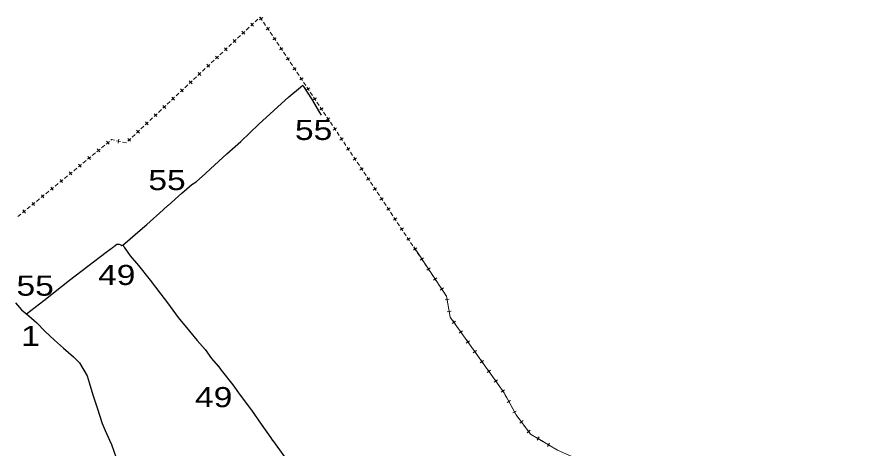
# Model space of a CAD drawing. Extents: x 476989 to 498418, y 4381813 to 4416555.
# Drawn here: x 485532 to 487660, y 4388253 to 4389328 of the extents above; entities that cross this region are included whole.
import ezdxf
from ezdxf.enums import TextEntityAlignment as Align

# ---------------------------------------------------------------- set-up
doc = ezdxf.new("R2010")
doc.units = 0
doc.header["$LTSCALE"] = 20
for name, color, linetype, lineweight in [('13', 7, 'Continuous', 13), ('34', 7, 'Continuous', 13), ('6', 7, 'Continuous', 25)]:
    doc.layers.add(name, color=color, linetype=linetype, lineweight=lineweight)

msp = doc.modelspace()

# ---------------------------------------------------------------- linework, layer by layer
at = {"layer": '34'}
for p, q in [((486136.45, 4389326.54), (486138, 4389328)), ((486144.93, 4389326.63), (486136.62, 4389321.07)), ((486138, 4389328), (486143.56, 4389319.7)), ((486114.56, 4389306.04), (486121.86, 4389312.87)), ((486114.79, 4389313.1), (486121.63, 4389305.81)), ((486125.51, 4389316.29), (486132.81, 4389323.13)), ((486146.34, 4389315.54), (486151.9, 4389307.23)), ((486092.68, 4389285.53), (486099.98, 4389292.37)), ((486092.91, 4389292.6), (486099.75, 4389285.3)), ((486103.63, 4389295.79), (486110.92, 4389302.62)), ((486161.61, 4389301.71), (486153.3, 4389296.15)), ((486154.67, 4389303.08), (486160.23, 4389294.77)), ((486163.01, 4389290.62), (486168.57, 4389282.3)), ((486070.8, 4389265.02), (486078.09, 4389271.86)), ((486071.03, 4389272.09), (486077.86, 4389264.79)), ((486081.74, 4389275.28), (486089.04, 4389282.12)), ((486178.28, 4389276.78), (486169.97, 4389271.22)), ((486171.35, 4389278.16), (486176.91, 4389269.85)), ((486179.69, 4389265.69), (486185.25, 4389257.38)), ((486048.91, 4389244.52), (486056.21, 4389251.35)), ((486049.14, 4389251.58), (486055.98, 4389244.29)), ((486059.86, 4389254.77), (486067.16, 4389261.61)), ((486194.96, 4389251.86), (486186.65, 4389246.3)), ((486188.02, 4389253.23), (486193.59, 4389244.92)), ((486016.09, 4389213.76), (486023.39, 4389220.6)), ((486027.03, 4389224.01), (486034.33, 4389230.85)), ((486027.26, 4389231.08), (486034.1, 4389223.78)), ((486037.98, 4389234.27), (486045.27, 4389241.1)), ((486196.37, 4389240.76), (486201.93, 4389232.45)), ((486211.64, 4389226.93), (486203.33, 4389221.37)), ((486204.7, 4389228.31), (486210.26, 4389219.99)), ((485994.21, 4389193.25), (486001.51, 4389200.09)), ((486005.15, 4389203.5), (486012.45, 4389210.34)), ((486005.38, 4389210.57), (486012.22, 4389203.27)), ((486213.04, 4389215.84), (486218.6, 4389207.53)), ((486228.31, 4389202.01), (486220, 4389196.44)), ((486221.38, 4389203.38), (486226.94, 4389195.07)), ((485972.33, 4389172.74), (485979.62, 4389179.58)), ((485983.27, 4389182.99), (485990.56, 4389189.83)), ((485983.5, 4389190.06), (485990.33, 4389182.77)), ((486229.72, 4389190.91), (486235.28, 4389182.6)), ((486238.06, 4389178.45), (486243.62, 4389170.14)), ((485950.45, 4389152.24), (485957.74, 4389159.08)), ((485961.38, 4389162.49), (485968.68, 4389169.33)), ((485961.61, 4389169.55), (485968.45, 4389162.26)), ((486244.99, 4389177.08), (486236.68, 4389171.52)), ((486246.4, 4389165.99), (486251.96, 4389157.68)), ((485928.56, 4389131.73), (485935.86, 4389138.57)), ((485939.5, 4389141.98), (485946.8, 4389148.82)), ((485939.73, 4389149.05), (485946.57, 4389141.75)), ((486261.67, 4389152.15), (486253.36, 4389146.59)), ((486254.73, 4389153.53), (486260.29, 4389145.22)), ((486263.07, 4389141.06), (486268.63, 4389132.75)), ((485906.68, 4389111.22), (485913.98, 4389118.06)), ((485917.62, 4389121.47), (485924.91, 4389128.31)), ((485917.85, 4389128.54), (485924.68, 4389121.24)), ((486278.35, 4389127.23), (486270.03, 4389121.67)), ((486271.41, 4389128.6), (486276.97, 4389120.29)), ((486279.75, 4389116.14), (486285.31, 4389107.83)), ((485884.8, 4389090.72), (485892.09, 4389097.55)), ((485895.73, 4389100.97), (485903.03, 4389107.8)), ((485895.96, 4389108.03), (485902.8, 4389100.74)), ((486295.02, 4389102.3), (486286.71, 4389096.74)), ((486288.09, 4389103.68), (486293.65, 4389095.37)), ((485862.91, 4389070.21), (485870.21, 4389077.05)), ((485873.85, 4389080.46), (485881.15, 4389087.3)), ((485874.08, 4389087.53), (485880.92, 4389080.23)), ((486296.43, 4389091.21), (486301.99, 4389082.9)), ((486311.7, 4389077.38), (486303.39, 4389071.82)), ((486304.76, 4389078.75), (486310.32, 4389070.44)), ((485841.03, 4389049.7), (485848.33, 4389056.54)), ((485851.97, 4389059.95), (485859.27, 4389066.79)), ((485852.2, 4389067.02), (485859.04, 4389059.72)), ((486313.1, 4389066.29), (486318.66, 4389057.97)), ((486328.38, 4389052.45), (486320.06, 4389046.89)), ((486321.44, 4389053.83), (486327, 4389045.52)), ((485819.15, 4389029.2), (485826.44, 4389036.03)), ((485830.09, 4389039.45), (485837.38, 4389046.28)), ((485830.31, 4389046.51), (485837.15, 4389039.22)), ((486329.78, 4389041.36), (486335.34, 4389033.05)), ((486338.12, 4389028.9), (486343.68, 4389020.59)), ((485743.01, 4389002.49), (485750.74, 4389008.83)), ((485754.59, 4389012), (485762.32, 4389018.34)), ((485755.29, 4389019.04), (485761.63, 4389011.31)), ((485780.35, 4389020.26), (485790.11, 4389018.09)), ((485786.31, 4389024.05), (485784.14, 4389014.29)), ((485808.2, 4389018.94), (485815.5, 4389025.78)), ((485808.43, 4389026.01), (485815.27, 4389018.71)), ((486345.05, 4389027.53), (486336.74, 4389021.97)), ((486346.46, 4389016.43), (486352.02, 4389008.12)), ((485719.82, 4388983.46), (485727.55, 4388989.81)), ((485731.41, 4388992.97), (485739.14, 4388999.32)), ((485732.1, 4389000.01), (485738.45, 4388992.28)), ((486361.73, 4389002.6), (486353.42, 4388997.04)), ((486354.79, 4389003.98), (486360.35, 4388995.66)), ((486363.13, 4388991.51), (486368.7, 4388983.2)), ((485696.64, 4388964.44), (485704.37, 4388970.78)), ((485708.23, 4388973.95), (485715.96, 4388980.29)), ((485708.92, 4388980.98), (485715.27, 4388973.25)), ((486378.41, 4388977.68), (486370.09, 4388972.11)), ((486371.47, 4388979.05), (486377.03, 4388970.74)), ((486379.81, 4388966.58), (486385.37, 4388958.27)), ((485673.46, 4388945.41), (485681.19, 4388951.76)), ((485685.05, 4388954.92), (485692.78, 4388961.27)), ((485685.74, 4388961.96), (485692.08, 4388954.23)), ((486395.08, 4388952.75), (486386.77, 4388947.19)), ((486388.15, 4388954.12), (486393.71, 4388945.81)), ((485638.68, 4388916.87), (485646.41, 4388923.22)), ((485639.37, 4388923.91), (485645.72, 4388916.18)), ((485650.28, 4388926.39), (485658.01, 4388932.73)), ((485661.86, 4388935.9), (485669.59, 4388942.24)), ((485662.56, 4388942.93), (485668.9, 4388935.2)), ((486396.49, 4388941.66), (486402.05, 4388933.35)), ((486411.76, 4388927.82), (486403.45, 4388922.26)), ((486404.82, 4388929.2), (486410.38, 4388920.89)), ((485615.5, 4388897.85), (485623.23, 4388904.19)), ((485616.19, 4388904.88), (485622.54, 4388897.15)), ((485627.09, 4388907.36), (485634.82, 4388913.71)), ((486413.16, 4388916.73), (486418.73, 4388908.42)), ((486428.44, 4388902.9), (486420.13, 4388897.34)), ((486421.5, 4388904.27), (486427.06, 4388895.96)), ((485592.32, 4388878.82), (485600.05, 4388885.16)), ((485593.01, 4388885.86), (485599.35, 4388878.13)), ((485603.91, 4388888.34), (485611.64, 4388894.68)), ((486429.84, 4388891.81), (486435.4, 4388883.5)), ((485569.13, 4388859.8), (485576.86, 4388866.14)), ((485569.83, 4388866.83), (485576.17, 4388859.1)), ((485580.73, 4388869.31), (485588.46, 4388875.66)), ((486445.11, 4388877.97), (486436.8, 4388872.41)), ((486438.18, 4388879.35), (486443.74, 4388871.04)), ((486446.52, 4388866.88), (486452.08, 4388858.57)), ((485534.36, 4388831.26), (485542.09, 4388837.6)), ((485545.95, 4388840.77), (485553.68, 4388847.11)), ((485546.64, 4388847.81), (485552.99, 4388840.08)), ((485557.55, 4388850.29), (485565.28, 4388856.63)), ((486461.79, 4388853.05), (486453.48, 4388847.49)), ((486454.85, 4388854.42), (486460.41, 4388846.11)), ((486463.2, 4388841.96), (486468.76, 4388833.64)), ((486478.47, 4388828.12), (486470.16, 4388822.56)), ((486471.53, 4388829.5), (486477.09, 4388821.19)), ((486479.87, 4388817.03), (486485.43, 4388808.72)), ((486495.14, 4388803.2), (486486.83, 4388797.64)), ((486488.21, 4388804.57), (486493.77, 4388796.26)), ((486496.55, 4388792.1), (486502.11, 4388783.79)), ((486511.82, 4388778.27), (486503.51, 4388772.71)), ((486504.88, 4388779.65), (486510.45, 4388771.33)), ((486513.23, 4388767.18), (486518.79, 4388758.87)), ((486528.5, 4388753.35), (486520.19, 4388747.78)), ((486521.56, 4388754.72), (486527.12, 4388746.41)), ((486529.9, 4388742.25), (486535.46, 4388733.94)), ((486545.17, 4388728.42), (486536.86, 4388722.86)), ((486538.24, 4388729.79), (486543.8, 4388721.48)), ((486546.58, 4388717.33), (486552.14, 4388709.02)), ((486561.85, 4388703.49), (486553.54, 4388697.93)), ((486554.91, 4388704.87), (486560.48, 4388696.56)), ((486563.26, 4388692.4), (486568.82, 4388684.09)), ((486578.53, 4388678.57), (486570.22, 4388673.01)), ((486571.59, 4388679.94), (486577.15, 4388671.63)), ((486579.93, 4388667.48), (486585.49, 4388659.17)), ((486595.2, 4388653.64), (486586.89, 4388648.08)), ((486588.27, 4388655.02), (486593.83, 4388646.71)), ((486596.61, 4388642.55), (486602.17, 4388634.24)), ((486609.38, 4388625.48), (486599.52, 4388623.77)), ((486603.6, 4388629.55), (486605.3, 4388619.7)), ((486606.15, 4388614.77), (486607.86, 4388604.92)), ((486614.49, 4388595.93), (486604.64, 4388594.22)), ((486608.71, 4388600), (486610.42, 4388590.15)), ((486625.19, 4388571.11), (486617.04, 4388565.31)), ((486618.21, 4388572.28), (486624.02, 4388564.14)), ((486626.92, 4388560.07), (486632.72, 4388551.92)), ((486642.59, 4388546.69), (486634.45, 4388540.89)), ((486635.62, 4388547.86), (486641.42, 4388539.72)), ((486644.33, 4388535.65), (486650.13, 4388527.5)), ((486660, 4388522.27), (486651.86, 4388516.47)), ((486653.03, 4388523.44), (486658.83, 4388515.3)), ((486661.73, 4388511.22), (486667.54, 4388503.08)), ((486677.41, 4388497.85), (486669.26, 4388492.04)), ((486670.43, 4388499.02), (486676.24, 4388490.88)), ((486679.14, 4388486.8), (486684.94, 4388478.66)), ((486694.81, 4388473.43), (486686.67, 4388467.62)), ((486687.84, 4388474.6), (486693.64, 4388466.45)), ((486696.55, 4388462.38), (486702.35, 4388454.24)), ((486712.22, 4388449.01), (486704.08, 4388443.2)), ((486705.25, 4388450.18), (486711.05, 4388442.03)), ((486713.95, 4388437.96), (486719.76, 4388429.82)), ((486729.63, 4388424.58), (486721.48, 4388418.78)), ((486722.65, 4388425.75), (486728.46, 4388417.61)), ((486731.36, 4388413.54), (486737.16, 4388405.4)), ((486747.03, 4388400.16), (486738.89, 4388394.36)), ((486740.06, 4388401.33), (486745.86, 4388393.19)), ((486748.28, 4388388.81), (486753.07, 4388380.04)), ((486762.24, 4388373.66), (486753.47, 4388368.87)), ((486755.46, 4388375.66), (486760.25, 4388366.88)), ((486762.64, 4388362.49), (486767.43, 4388353.71)), ((486769.82, 4388349.33), (486774.61, 4388340.55)), ((486776.61, 4388347.33), (486767.83, 4388342.54)), ((486777.26, 4388336.32), (486783.26, 4388328.32)), ((486793.25, 4388323.33), (486785.25, 4388317.33)), ((486786.25, 4388324.33), (486792.25, 4388316.33)), ((486795.25, 4388312.33), (486801.25, 4388304.33)), ((486811.25, 4388299.34), (486803.25, 4388293.34)), ((486804.25, 4388300.34), (486810.25, 4388292.34)), ((486813.78, 4388288.94), (486822.37, 4388283.81)), ((486826.65, 4388281.25), (486835.24, 4388276.12)), ((486833.51, 4388282.98), (486828.38, 4388274.39)), ((486839.53, 4388273.56), (486848.12, 4388268.44)), ((486852.4, 4388265.88), (486860.99, 4388260.75)), ((486859.26, 4388267.61), (486854.13, 4388259.02)), ((486865.28, 4388258.19), (486873.87, 4388253.06))]:
    msp.add_line(p, q, dxfattribs=at)
for points in [[(485766.19, 4389021.51), (485768, 4389023), (485775.48, 4389021.34)], [(485794.99, 4389017), (485804, 4389015), (485804.56, 4389015.53)], [(486520.9, 4388755.72), (486603, 4388633), (486612, 4388581), (486746, 4388393), (486776, 4388338), (486812, 4388290), (486879, 4388250), (487017, 4388189), (487152, 4388148), (487234, 4388140), (487360, 4387899), (487497, 4387717), (487531, 4387660), (487608, 4387440), (487634, 4387181), (487675, 4387065), (487547, 4387001), (487350, 4386921), (487175, 4386900), (487110, 4386912), (487380, 4386493), (487280.6, 4386441.97)], [(486611.27, 4388585.22), (486612, 4388581), (486615.32, 4388576.35)]]:
    msp.add_lwpolyline(points, dxfattribs=at)
at = {"layer": '6'}
for p, q in [((485796.06, 4388760.1), (485844.58, 4388802.43)), ((485796.2, 4388760.11), (485798.58, 4388757.09)), ((486033.72, 4388459.48), (486041.26, 4388448.96))]:
    msp.add_line(p, q, dxfattribs=at)
for points in [[(486001.93, 4388938.61), (486014.55, 4388950.06), (486055.52, 4388987.26), (486089.93, 4389018.56), (486134.81, 4389061.03), (486172.22, 4389095.85), (486209.9, 4389129.16), (486238.99, 4389153.84), (486244.36, 4389158.81)], [(486244.36, 4389158.81), (486246.3, 4389155.36), (486266.08, 4389124.41), (486285.79, 4389090.61), (486290.28, 4389083.44)], [(485908.72, 4388859.13), (485942.82, 4388889.38), (485967.78, 4388911.23), (485979.12, 4388917.87), (486002.07, 4388938.75)], [(485845.07, 4388802.86), (485855.41, 4388811.97), (485896.23, 4388848.05), (485908.32, 4388858.96)], [(485556.22, 4388588.91), (485598.98, 4388622.45), (485662.95, 4388672.73), (485708.55, 4388708.04), (485754.62, 4388742.62), (485772.47, 4388756.23)], [(485773.67, 4388757.14), (485780.73, 4388762.52), (485783.72, 4388762.91), (485786.72, 4388762.91), (485790.86, 4388761.38), (485793.38, 4388759.69), (485796.06, 4388760.1)], [(485799.02, 4388756.18), (485799.28, 4388755.64), (485814.2, 4388733.49), (485834.73, 4388709.28), (485864.11, 4388672.95), (485890.94, 4388638.49), (485907.48, 4388616.48), (485933.57, 4388580.5), (485961.99, 4388546.41), (485980.86, 4388522.5), (486000.92, 4388500.56), (486016.79, 4388478.01), (486033.78, 4388459.37)], [(485528.76, 4388616.39), (485543.57, 4388599.11), (485561.47, 4388584.67), (485581.34, 4388566.46), (485601.43, 4388546.21), (485625.33, 4388523.43), (485648.4, 4388503.95), (485672.73, 4388482.48), (485688.17, 4388467.01), (485707.06, 4388435), (485712.35, 4388418.05), (485721.25, 4388387.26), (485731.78, 4388354.89), (485744.85, 4388316.19), (485751.85, 4388298.7), (485762.78, 4388274.7), (485768, 4388263.85), (485779.02, 4388230.66)], [(486041.26, 4388448.96), (486070.33, 4388412.2), (486088.62, 4388386.55), (486116.6, 4388349.44), (486140.39, 4388314.86), (486164.8, 4388280.35), (486169.29, 4388274.24)], [(486169.13, 4388274.35), (486186.31, 4388250.53), (486213.19, 4388213.09), (486235.61, 4388178.6), (486251.45, 4388155.76), (486271.85, 4388125.77), (486296.82, 4388088.37), (486314.6, 4388061.76), (486330.73, 4388040.49), (486349.4, 4388018.73), (486364.43, 4388000.31), (486372.86, 4387995.35), (486382.16, 4387992.25)]]:
    msp.add_lwpolyline(points, dxfattribs=at)

# ---------------------------------------------------------------- texts
at = {"layer": '13', "width": 1.25}
for p in [(486271.45, 4389022.13), (485906.05, 4388897.3)]:
    msp.add_text('55', height=50, dxfattribs=at).set_placement(p, align=Align.CENTER)
at = {"layer": '6', "width": 1.25}
for s, p in [('49', (485780.75, 4388661)), ('55', (485577.39, 4388634.42)), ('1', (485565.93, 4388509.28)), ('49', (486022.33, 4388356.95))]:
    msp.add_text(s, height=50, dxfattribs=at).set_placement(p, align=Align.CENTER)

doc.saveas('drawing.dxf')
